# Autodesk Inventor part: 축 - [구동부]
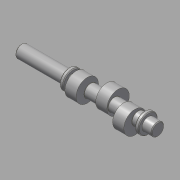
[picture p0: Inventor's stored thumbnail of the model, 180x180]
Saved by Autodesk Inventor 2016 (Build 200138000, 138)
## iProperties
Company: 한국ATC센터
Created: 2014-08
Part Number: 축 - [구동부]
Document SubType Name: Modeling
Designer: KYOUNG IL JANG
Density: 7.86 g/cm^3
Material: 강철, 연강
Appearance: 강철
Author: KYOUNG IL JANG
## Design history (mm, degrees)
sketch "스케치1"
  geometry: L1 (-91.5, 0)-(91.5, 0); L2 (-91.5, 0)-(-91.5, 8.5); L3 (-91.5, 8.5)-(-27.5, 8.5); L4 (-27.5, 8.5)-(-27.5, 13); L5 (-27.5, 13)-(-22.5, 13); L6 (-22.5, 13)-(-22.5, 8.5); L7 (-22.5, 8.5)-(73.5, 8.5); L8 (73.5, 8.5)-(73.5, 13); L9 (73.5, 13)-(78.5, 13); L10 (78.5, 13)-(78.5, 8.5); L11 (78.5, 8.5)-(91.5, 8.5); L12 (91.5, 8.5)-(91.5, 0); 2 further points
  constraints: 24 end point, 5 parallel, 1 coincident, 1 horizontal, 1 midpoint, 1 perpendicular
  dimensions: "d0" = 183 distance of L1.start L1.end (derived); "d2" = 17 diameter of L3 L1; "d3" = 26 diameter of L5 L1; "d4" = 17 diameter of L7 L1; "d5" = 26 diameter of L9 L1; "d6" = 17 diameter of L11 L1; "d7" = 5 distance of L8.end L9.end; "d8" = 5 distance of L4.end L5.end; "d10" = 64 distance of L2.end L3.end; "d11" = 13 distance of L10.end L11.end; "d35" = 96 distance between parallel lines of L8 L6
revolve "회전1" sketch "스케치1" stored, may be unused: angle "d12" = 90 deg
node "작업 평면7"
sketch "스케치6"
  geometry: C1 r 15 at (0, 5); 1 further point
  constraints: 1 centre point, 1 vertical alignment
  dimensions: "d37" = 30 diameter of C1; "d38" = 5 distance of C1.centre point (0, 0)
extrude "돌출4" join sketch "스케치6" stored distance "d33" = 15; taper "d34" = 0 deg
node "작업 평면8"
sketch "스케치7"
  geometry: L1 (0, 0)-(-6.5, -11.258); L2 (0, 0)-(13, 0); C1 r 15 at (-2.5, -4.33); A1 r 13 centre (0, 0) between (-6.5, -11.258) and (13, 0) reference; 1 further point
  constraints: 4 end point, 2 point on circle, 1 centre point, 1 horizontal, 1 point on line
  dimensions: "d40" = 120 deg angle of L1 L2; "d41" = 30 diameter of C1; "d42" = 5 distance of point (0, 0) C1.centre
extrude "돌출5" join sketch "스케치7" stored distance "d43" = 15; taper "d44" = 0 deg
node "작업 평면9"
sketch "스케치8"
  geometry: L1 (0, 0)-(4.25, -7.361); L2 (0, 0)-(-8.5, 0); C1 r 15 at (2.5, -4.33); A1 r 8.5 centre (0, 0) between (4.25, -7.361) and (-8.5, 0) reference; 1 further point
  constraints: 4 end point, 2 point on circle, 1 centre point, 1 horizontal, 1 point on line
  dimensions: "d46" = 120 deg angle of L1 L2; "d47" = 30 diameter of C1; "d48" = 5 distance of point (0, 0) C1.centre
extrude "돌출6" join sketch "스케치8" stored distance "d49" = 15; taper "d50" = 0 deg
node "작업 평면3"
sketch "스케치5"
  geometry: L1 (32, 8.5)-(32, -8.5) reference; L2 (27.5, -2.5)-(14.5, -2.5); L3 (14.5, 2.5)-(27.5, 2.5); A1 r 2.5 centre (14.5, 0) between (14.5, 2.5) and (14.5, -2.5); A2 r 2.5 centre (27.5, 0) between (27.5, -2.5) and (27.5, 2.5); 4 further points
  constraints: 4 end point, 4 point on circle, 4 tangent, 2 centre point, 2 point on line, 1 horizontal alignment, 1 midpoint, 1 parallel, 1 perpendicular
  dimensions: "d23" = 5 distance between parallel lines of L3 L2; "d36" = 20 dimension on A1 L1; "d52" = 2 distance edge to line of A2 L1
extrude "돌출3" cut sketch "스케치5" distance "d25" = 3; taper "d26" = 0 deg
chamfer "모따기1" distance "d27" = 1; stored, may be unused: second distance "d28" = 2, angle "d29" = 45 deg
fillet "모깎기1" dims "d51" = 0.3
chamfer "모따기2" distance "d53" = 1; stored, may be unused: second distance "d54" = 2, angle "d55" = 45 deg
node "작업 평면10"
node "솔리드1"
other parameters: "d39" = -32, "d45" = 32
